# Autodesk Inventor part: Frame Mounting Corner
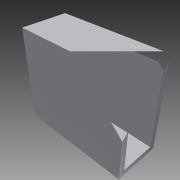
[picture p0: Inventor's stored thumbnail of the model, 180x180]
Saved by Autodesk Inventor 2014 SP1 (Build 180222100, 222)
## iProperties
Created: 2014-06
Part Number: Frame Mounting Corner
Material: Aluminum 6061
Document SubType Name: Modeling
Designer: Michael
Density: 2.71 g/cm^3
Appearance: Aluminum - Flat
Mass: 72.5115 g
Surface Area: 177.419 cm^2
Volume: 26.757 cm^3
Author: Michael
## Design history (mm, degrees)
sketch "Sketch1"
  geometry: L1 (-30.163, -25.4)-(30.163, -25.4); L2 (30.163, -25.4)-(30.163, 25.4); L3 (30.163, 25.4)-(-30.162, 25.4); L4 (-30.162, 25.4)-(-30.163, -25.4); L5 (-30.163, -25.4)-(30.163, 25.4); L6 (30.163, -25.4)-(-30.162, 25.4); 1 further point
  constraints: 12 end point, 2 midpoint, 2 parallel, 1 horizontal, 1 perpendicular
  dimensions: "d0" = 60.325 distance of L3.end L2.end; "d1" = 50.8 distance between parallel lines of L1 L3
extrude "Extrusion1" new body sketch "Sketch1" distance "d2" = 25.4; taper "d3" = 0 deg
sketch "Sketch2"
  geometry: L1 (0, 0)-(0, 50.8) reference; L2 (0, 50.8)-(-25.4, 50.8) reference; L3 (-25.4, 0)-(-25.4, 50.8) reference; L4 (0, 0)-(-25.4, 0) reference; L5 (-3.175, 47.625)-(-3.175, 3.175); L6 (-3.175, 3.175)-(-22.225, 3.175); L7 (-22.225, 3.175)-(-22.225, 47.625); L8 (-22.225, 47.625)-(-3.175, 47.625); 1 further point
  constraints: 8 end point, 3 other
  dimensions: "d4" = 3.175 distance between parallel lines of L2 L8
extrude "Extrusion2" cut sketch "Sketch2" stored distance "d5" = 25.4; taper "d6" = 0 deg
body "Solid1"
